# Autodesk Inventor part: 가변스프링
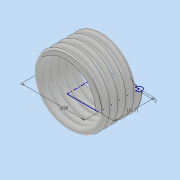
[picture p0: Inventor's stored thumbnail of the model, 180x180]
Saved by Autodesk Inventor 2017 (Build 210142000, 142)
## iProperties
Part Number: 가변스프링
Material: 일반
Document SubType Name: Modeling
Designer: mrc
Density: 1 g/cm^3
Appearance: 기본값
Author: mrc
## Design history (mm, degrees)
sketch "스케치1"
  geometry: L1 (0, -12.7)-(10, -12.7); L2 (10, -12.7)-(10, 0); L3 (10, 0)-(0, 0); L4 (0, 0)-(0, -12.7); C1 r 1 at (10, 0); 1 further point
  constraints: 8 end point, 2 coincident, 2 parallel, 1 centre point, 1 horizontal, 1 perpendicular
  dimensions: "d0" = 12.7 distance between parallel lines of L3 L1 (derived); "d1" = 20 diameter of L2 L4; "d2" = 2 diameter of C1
feature "코일2" sketch "스케치1" pitch "d14" = 10; turns "d16" = 5; dims "d15" = 12.7 (= d0), "d17" = 0, angle "d18" = 90 deg, angle "d19" = 90 deg, "d20" = 0, "d21" = 0
sketch "스케치3"
  geometry: L1 (-20, -12.7)-(20, -12.7); L2 (20, -12.7)-(20, 0); L3 (20, 0)-(-20, 0); L4 (-20, 0)-(-20, -12.7); L5 (0, 0)-(0, -12.7) reference; 2 further points
  constraints: 8 end point, 2 midpoint, 2 parallel, 1 coincident, 1 horizontal, 1 perpendicular
  dimensions: "d22" = 40 distance of L1.start L1.end
extrude "돌출2" sketch "스케치3" stored distance "d23" = 0; taper "d24" = 0 deg
node "솔리드2"
